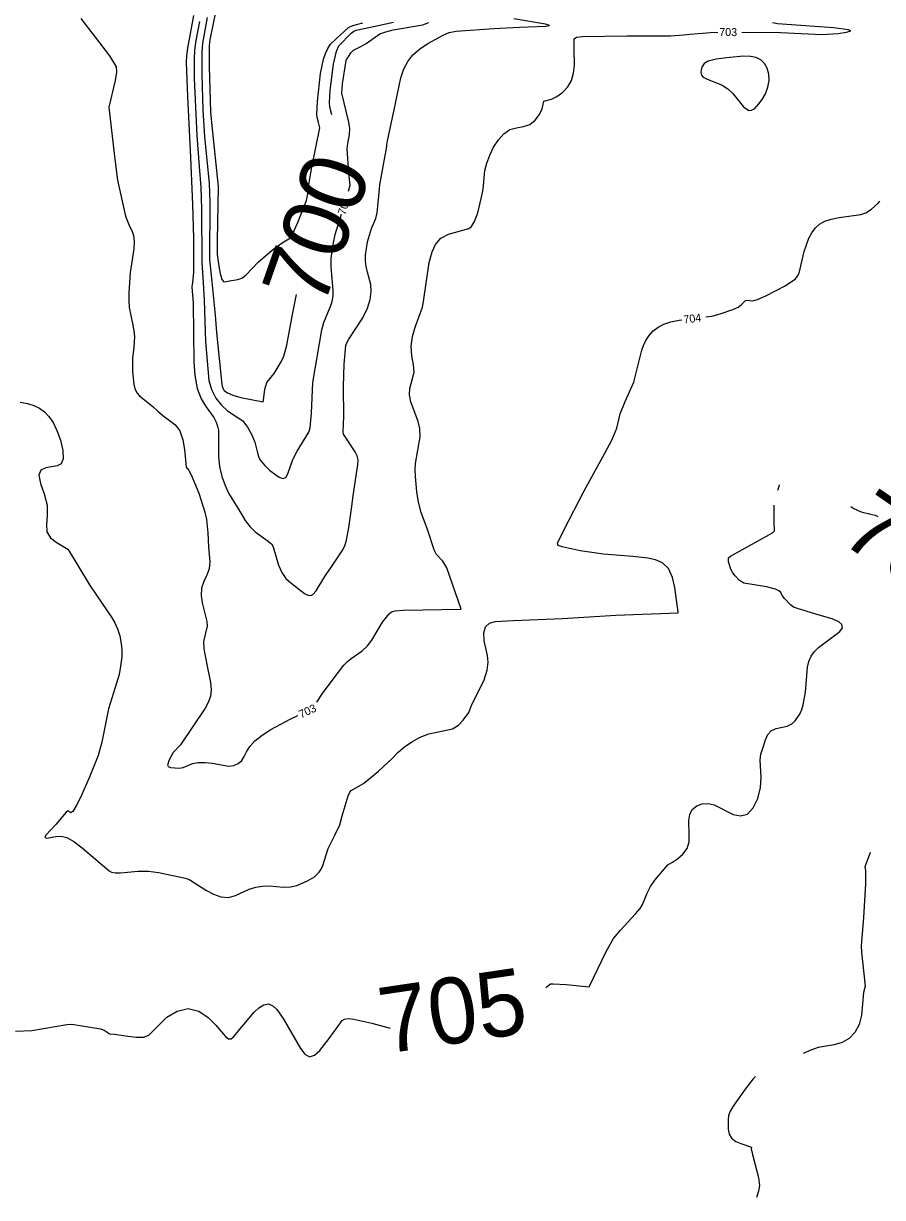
# Model space of a CAD drawing. Extents: x -291892836 to 2945206, y -477993085 to 1832792.
# Drawn here: x 1853557 to 1853987, y 544335 to 544921 of the extents above; entities that cross this region are included whole.
import ezdxf

# ---------------------------------------------------------------- set-up
doc = ezdxf.new("R2010")
doc.units = 0
for name, color, linetype in [('DT_X_Contour_Minor', 7, 'Continuous'), ('DT_X_Terrain_Ground_Line', 7, 'Continuous'), ('Level 19', 7, 'Continuous')]:
    doc.layers.add(name, color=color, linetype=linetype)

msp = doc.modelspace()

# ---------------------------------------------------------------- linework, layer by layer
at = {"layer": 'DT_X_Contour_Minor'}
for points in [[(1853585.96, 544923.91), (1853600.19, 544905.28), (1853603.63, 544899.82), (1853603.71, 544897.14), (1853603.01, 544892.88), (1853599.97, 544879.67), (1853602.72, 544854.89), (1853604.29, 544843.16), (1853608.28, 544825.1), (1853610.33, 544820.16), (1853611.4, 544817.92), (1853612.25, 544815.46), (1853612.64, 544812.49), (1853612.39, 544808.81), (1853610.66, 544796.97), (1853610, 544786.83), (1853609.92, 544783.29), (1853610.17, 544779.51), (1853611.75, 544771.47), (1853612.45, 544767.83), (1853612.71, 544764.81), (1853612.34, 544759.71), (1853611.83, 544754.16), (1853611.73, 544747.54), (1853612.39, 544741.05), (1853613.07, 544738.6), (1853614.01, 544736.74), (1853615.21, 544735.35), (1853622.15, 544729.95), (1853624.37, 544727.73), (1853626.98, 544725.5), (1853632.99, 544721.05), (1853633.91, 544719.84)], [(1853642.34, 544925.33), (1853639.2, 544909.11), (1853638.71, 544905.29), (1853638.6, 544901.98), (1853639.34, 544884.86), (1853640.71, 544854.54), (1853641.8, 544831.05), (1853642.2, 544814.23), (1853642.31, 544797.24), (1853641.82, 544792.08), (1853641.36, 544789.86), (1853642.15, 544781.74), (1853642.44, 544752.42), (1853642.98, 544745.62), (1853644.15, 544739.08), (1853646.11, 544733.94), (1853648.46, 544730.07), (1853652.4, 544724.48), (1853653.57, 544722.24), (1853654.3, 544720.22), (1853654.68, 544718.3), (1853654.77, 544713.26), (1853654.8, 544704.9), (1853655.34, 544700), (1853656.5, 544695.1), (1853658.08, 544690.56), (1853659.8, 544686.75), (1853663.03, 544681.5), (1853666.22, 544676.23), (1853668.08, 544673.1), (1853670.37, 544670.06), (1853673.17, 544667.38), (1853678.45, 544663.59), (1853681.24, 544661.52), (1853682.02, 544659.9), (1853684.7, 544650.75), (1853686.36, 544647.06), (1853687.06, 544646.11)], [(1853649.17, 544924.37), (1853646.8, 544911.58), (1853646.44, 544907.11), (1853646.36, 544895.69), (1853646.98, 544878.04), (1853647.82, 544865.03), (1853650.15, 544841.42), (1853650.38, 544832.08), (1853650.34, 544803.47), (1853651.42, 544792.36), (1853653.16, 544775.72), (1853653.71, 544767.02), (1853656.39, 544741.1), (1853656.82, 544739.49), (1853657.63, 544738.12), (1853659.19, 544736.86), (1853661.91, 544735.68), (1853665.94, 544734.59), (1853677.1, 544732.4), (1853677.24, 544733.27), (1853678, 544738.78), (1853678.95, 544742.01), (1853682.56, 544746.61), (1853686.15, 544752.45), (1853687.37, 544755.19), (1853688.9, 544760.64), (1853691.63, 544775.14), (1853693.7, 544786.01)], [(1853653.38, 544927.84), (1853650.47, 544913.18), (1853650.14, 544910.21), (1853650.11, 544899.8), (1853650.68, 544877.35), (1853651.38, 544870.27), (1853654.61, 544839.99), (1853654.13, 544812.84), (1853654.14, 544805.94), (1853654.85, 544800.17), (1853655.51, 544796.44), (1853656.36, 544793.56), (1853657.39, 544792.38), (1853658.66, 544792.43), (1853660.27, 544792.88), (1853664.37, 544793.44), (1853666.47, 544794.17), (1853668.37, 544795.64), (1853674.77, 544802.39), (1853682.58, 544808.93), (1853686.54, 544811.87), (1853690.72, 544814.35), (1853691.62, 544815.77), (1853694.44, 544822.07), (1853698.7, 544833.04), (1853699.46, 544836.24), (1853699.75, 544839.97), (1853701.47, 544849.64), (1853705.39, 544869.24), (1853704.84, 544871.98), (1853704.15, 544874.47), (1853703.98, 544876.07), (1853704.28, 544882.49), (1853705.78, 544896.38), (1853707.19, 544903.57), (1853708.21, 544906.48), (1853709.44, 544908.96), (1853710.84, 544911.01), (1853713.92, 544914.01), (1853717.83, 544917.62), (1853719.76, 544919.37), (1853721.97, 544920.46), (1853726.92, 544921.78)], [(1853735.2, 544838.78), (1853735.39, 544840.73), (1853737.42, 544851.86), (1853738.94, 544859.98), (1853738.85, 544860.72), (1853739.21, 544862.74), (1853742.62, 544878.24), (1853745.92, 544894.2), (1853747.44, 544898.69), (1853749.41, 544902.49), (1853751.99, 544905.7), (1853755.33, 544908.61), (1853759.47, 544911.42), (1853767.51, 544915.82), (1853770.11, 544916.9), (1853773.58, 544917.58), (1853792.47, 544918.97), (1853805.19, 544919.58), (1853818.36, 544920.04), (1853820.21, 544920.43), (1853818.33, 544921.03), (1853802.45, 544923.79)], [(1853645.28, 544922.46), (1853643.47, 544912.94), (1853642.82, 544908.11), (1853642.51, 544903.46), (1853642.61, 544894.01), (1853643.92, 544865.38), (1853645.12, 544849.95), (1853645.85, 544839.63), (1853646.19, 544828.58), (1853646.4, 544801.97), (1853647.02, 544791.92), (1853647.66, 544783.13), (1853648.18, 544762.54), (1853649.89, 544743.12), (1853651.19, 544738.49), (1853653.43, 544734.25), (1853656.29, 544730.66), (1853659.26, 544727.97), (1853666.85, 544722.85), (1853669.25, 544719.73), (1853671.39, 544715.96), (1853672.98, 544712.28)], [(1853711.42, 544875.75), (1853710.41, 544879.69), (1853710.25, 544881.87), (1853710.61, 544887.94), (1853712.33, 544901.05), (1853713.68, 544907.55), (1853715, 544910.23), (1853721.17, 544916.54), (1853722.41, 544917.65), (1853723.56, 544918.06), (1853730.77, 544919.63), (1853742.29, 544922.12)], [(1853719.72, 544837.68), (1853720.62, 544840.67), (1853719.94, 544846.78), (1853719.1, 544858.84), (1853719.51, 544861.44), (1853720.33, 544865.91), (1853720.36, 544868.89), (1853719.88, 544872.12), (1853716.37, 544886.68), (1853716.81, 544891.26), (1853718.58, 544902.87), (1853719.36, 544904.68), (1853719.7, 544904.81), (1853720.93, 544906.75), (1853722.19, 544908.03), (1853726.34, 544910.17), (1853728.66, 544911.39), (1853735.41, 544916.19), (1853738.37, 544917.32), (1853742.07, 544918.17), (1853756.98, 544920.76), (1853759.99, 544921.85)], [(1853916.39, 544917.08), (1853935.73, 544916.91), (1853956.45, 544915.92), (1853964.64, 544916.5), (1853968.83, 544917.05), (1853970.92, 544917.67), (1853969.73, 544918.26), (1853962.31, 544919.19), (1853934.33, 544921.21), (1853931.78, 544921.73)], [(1853832.66, 544908.76), (1853832.66, 544908.78), (1853832.63, 544913.79), (1853833.75, 544914.64), (1853836.73, 544914.94), (1853858.95, 544915.22), (1853870.34, 544915.22), (1853880.74, 544915.28), (1853887.25, 544915.76)], [(1853887.25, 544915.76), (1853890.61, 544916.01), (1853900.78, 544917), (1853904.39, 544917.06)], [(1853703.92, 544582.31), (1853706.69, 544586.74), (1853712.55, 544594.55), (1853717.49, 544600.76), (1853719.23, 544602.62), (1853721.17, 544604.21), (1853726.56, 544608.04), (1853729.23, 544610.5), (1853731.36, 544613.38), (1853736.78, 544622.35), (1853740.11, 544626.44), (1853741.22, 544627.5), (1853743.1, 544628.02), (1853747.2, 544628.24), (1853776.16, 544628.74), (1853768.87, 544649.51), (1853766.86, 544652.7), (1853763.71, 544656.1), (1853762.63, 544658.46), (1853759.33, 544668.61), (1853756.06, 544677.05), (1853754.83, 544682.2), (1853753.92, 544687.41), (1853753.19, 544695.01), (1853753.12, 544698.63), (1853753.34, 544701.54), (1853755.52, 544714.98), (1853755.43, 544719.01), (1853754.63, 544722.52), (1853750.96, 544732.38), (1853750.34, 544735.85), (1853750.39, 544739.02), (1853752.6, 544747.15), (1853752.21, 544750.91), (1853751.47, 544755.34), (1853751.16, 544760.16), (1853751.83, 544765.06), (1853753.14, 544769.64), (1853756.74, 544779.67), (1853757.24, 544782.56), (1853760.1, 544801.97), (1853761.55, 544807.36), (1853763.21, 544810.96), (1853765.92, 544814.1), (1853769.77, 544816.11), (1853780, 544819), (1853781.29, 544820.04), (1853782.75, 544822.49), (1853784.37, 544826.87), (1853786.35, 544834.68), (1853787.05, 544838.67), (1853787.94, 544848.01), (1853788.89, 544851.62), (1853790.38, 544855.58), (1853792.33, 544859.56), (1853794.69, 544863.24), (1853797.42, 544866.3), (1853800.48, 544868.38), (1853803.82, 544869.36), (1853807.21, 544869.93), (1853810.4, 544870.99), (1853813.13, 544873.17), (1853815.25, 544875.99), (1853816.61, 544878.7), (1853817.46, 544882.57), (1853821.26, 544883.54), (1853823.94, 544884.94), (1853826.87, 544887.08), (1853829.45, 544889.8), (1853831.22, 544892.98), (1853832.24, 544896.57), (1853832.7, 544900.55), (1853832.66, 544908.76)], [(1853920, 544877.91), (1853921.31, 544878.1), (1853922.75, 544878.85), (1853924.94, 544881.23), (1853926.56, 544883.47), (1853928.22, 544886.31), (1853929.51, 544889.53), (1853930.08, 544892.9), (1853929.94, 544896.18), (1853929.17, 544899.11), (1853927.83, 544901.5), (1853925.96, 544903.28), (1853923.58, 544904.43), (1853920.71, 544904.98), (1853917.45, 544905.05), (1853910.21, 544904.45), (1853903.61, 544903.52), (1853899.64, 544902.57), (1853897.62, 544901.39), (1853896.51, 544899.56), (1853896.1, 544898.3), (1853895.94, 544896.93), (1853896.24, 544895.65), (1853897.15, 544894.59), (1853898.71, 544893.7), (1853906.53, 544890.65), (1853909.39, 544888.85), (1853911.89, 544886.39), (1853917.33, 544879.7), (1853920, 544877.91)], [(1853710.88, 544649.44), (1853716.68, 544658.01), (1853717.92, 544660.52), (1853718.81, 544663.32), (1853719.99, 544669.65), (1853721.39, 544680.09), (1853721.87, 544684.21), (1853724.51, 544701.04), (1853724.59, 544703.39), (1853724.14, 544705.34), (1853723.13, 544707.33), (1853717.24, 544716.27), (1853717.04, 544717.6), (1853717.44, 544724.96), (1853717.21, 544740.07), (1853717.61, 544751.21), (1853718.43, 544760.46), (1853718.77, 544761.58), (1853720, 544763.66), (1853726.86, 544774.42), (1853729.25, 544779.21), (1853730.63, 544783.6), (1853731.09, 544787.52), (1853730.86, 544791.03), (1853729.31, 544797.15), (1853728.59, 544799.96), (1853728.24, 544802.75), (1853728.28, 544805.65), (1853729.33, 544812.28), (1853731.26, 544818.91), (1853733.35, 544823.95), (1853734.1, 544826.86), (1853734.86, 544835.37), (1853735.2, 544838.78)], [(1853898.39, 544774.81), (1853901.4, 544775.15), (1853905.6, 544776.28), (1853911.91, 544778.52), (1853914.58, 544779.76), (1853916.17, 544780.86), (1853918.21, 544782.95), (1853919, 544783.16), (1853921.84, 544782.77), (1853924.35, 544783.49), (1853928.44, 544785.31), (1853937.78, 544790.24), (1853943.12, 544793.69), (1853944.36, 544795.1), (1853945.05, 544796.67), (1853947.62, 544807.5), (1853950.02, 544814.11), (1853951.47, 544816.9), (1853953.21, 544819.27), (1853955.32, 544821.16), (1853957.93, 544822.63), (1853961.18, 544823.73), (1853965.09, 544824.53), (1853975.87, 544825.95), (1853978.44, 544826.8), (1853981.23, 544828.57), (1853984.59, 544831.57), (1853985.47, 544832.57)], [(1853672.98, 544712.28), (1853674.24, 544706.96), (1853674.74, 544705), (1853675.65, 544703.26), (1853677.94, 544700.5), (1853680.22, 544698.21), (1853683.46, 544695.88), (1853685.12, 544694.79), (1853686.85, 544694.1), (1853688.35, 544694.51), (1853689.45, 544696.49), (1853691.94, 544703.62), (1853694.08, 544707.7), (1853699.92, 544717.16), (1853700.61, 544719.42), (1853701.23, 544726.7), (1853701.9, 544741.99), (1853706.49, 544768.37), (1853707.38, 544772.04), (1853709.73, 544777.66), (1853710.83, 544780.05), (1853711.63, 544782.47), (1853712.07, 544785.11), (1853712.12, 544788.17), (1853711.08, 544799.88), (1853711.16, 544803.94), (1853712.06, 544811.04), (1853713.16, 544815.94), (1853716.25, 544826.19)], [(1853676.74, 544490.48), (1853680.18, 544490.52), (1853687.27, 544489.95), (1853690.7, 544490.03), (1853693.9, 544490.71), (1853699.2, 544493.01), (1853702.69, 544495.07), (1853705.12, 544497.33), (1853706.12, 544498.85), (1853706.98, 544500.78), (1853709.64, 544509.21), (1853712.93, 544515.92), (1853715.37, 544520.98), (1853716.66, 544525.51), (1853719.59, 544535.52), (1853720.35, 544537.35), (1853721.03, 544538.24), (1853727.2, 544541.75), (1853734.83, 544547.82), (1853741.83, 544554.42), (1853744.66, 544557.27), (1853747.7, 544559.95), (1853751.37, 544562.54), (1853755.52, 544564.81), (1853759.86, 544566.45), (1853771.73, 544569.02), (1853774.77, 544570.92), (1853777.18, 544573.29), (1853779.93, 544577.16), (1853780.78, 544579.4), (1853781.25, 544580.73), (1853787.54, 544593.52), (1853789.18, 544598.32), (1853789.64, 544602.26), (1853789.21, 544605.67), (1853787.67, 544613.06), (1853787.49, 544616.92), (1853788.28, 544620.01), (1853790.28, 544621.81), (1853793.09, 544622.6), (1853802.08, 544623.12), (1853826.73, 544624.12), (1853853.37, 544625.76), (1853884.53, 544627.04), (1853884.65, 544627.35), (1853882.94, 544639.65), (1853881.73, 544644.67), (1853879.74, 544649.04), (1853876.82, 544651.91), (1853873.26, 544653.51), (1853869.5, 544654.35), (1853861.99, 544655.17), (1853847.28, 544656.3), (1853835.64, 544657.96), (1853826.59, 544659.88), (1853824.61, 544660.61), (1853824.33, 544661.78), (1853827.45, 544668.3), (1853837.54, 544687.9), (1853847.96, 544706.73), (1853851.47, 544713.32), (1853853.92, 544719.23), (1853855.54, 544726.38), (1853858.04, 544732.53), (1853862.51, 544742.2), (1853865.18, 544752.95), (1853866.48, 544758.23), (1853867.3, 544760.49), (1853868.49, 544762.96), (1853870.09, 544765.49), (1853872.1, 544767.81), (1853874.54, 544769.71), (1853877.48, 544771.2), (1853880.98, 544772.33), (1853885.04, 544773.17), (1853886.47, 544773.36)], [(1853555.57, 544732.16), (1853559.22, 544731.56), (1853562.44, 544730.58), (1853565.24, 544729.2), (1853567.72, 544727.39), (1853569.99, 544725.1), (1853572.06, 544722.11), (1853573.98, 544718.15), (1853575.69, 544713.19), (1853576.88, 544708.08), (1853577.13, 544703.91), (1853576.16, 544701.48), (1853574.17, 544700.38), (1853568.44, 544699.43), (1853565.93, 544698.25), (1853564.85, 544695.78), (1853565.74, 544691.62), (1853567.6, 544686.35), (1853569.06, 544680.8), (1853569.17, 544675.65), (1853568.73, 544671.15), (1853568.99, 544667.4), (1853570.82, 544664.48), (1853573.53, 544662.33), (1853579.39, 544658.78), (1853580.14, 544657.83), (1853583.96, 544651.52), (1853590.33, 544640.91), (1853596.59, 544631.58), (1853601.31, 544624.84), (1853602.99, 544622.02), (1853604.32, 544618.99), (1853605.36, 544615.44), (1853606.1, 544611.65), (1853606.47, 544608.07), (1853606.46, 544605.04), (1853605.83, 544600.35), (1853605.03, 544596.19), (1853603.15, 544589.67), (1853599.75, 544578.97), (1853596.45, 544562.31), (1853594.52, 544555.65), (1853590.01, 544544.5), (1853585.71, 544534.76), (1853583.6, 544530.51), (1853581.91, 544527.78), (1853580.85, 544527.1), (1853579.49, 544527.99), (1853578.55, 544527.37), (1853573.45, 544521.15), (1853568.38, 544515.81), (1853567.84, 544514.64), (1853568.8, 544514.39), (1853573.42, 544515.21), (1853576.02, 544515.33), (1853578.88, 544514.66), (1853582.34, 544512.77), (1853586.59, 544509.5), (1853600.09, 544498), (1853601.29, 544497.46), (1853603.02, 544497.12), (1853605.72, 544497.11), (1853614.52, 544497.87), (1853619.71, 544497.9), (1853624.74, 544497.29), (1853638.3, 544494.36), (1853640.46, 544493.56), (1853645.62, 544490.31), (1853648.75, 544488.3), (1853652.26, 544486.44), (1853655.97, 544485.12), (1853659.69, 544484.78), (1853663.26, 544485.67), (1853670.05, 544488.9), (1853673.38, 544489.98), (1853676.74, 544490.48)], [(1853633.91, 544719.84), (1853635.44, 544717.82), (1853636.94, 544713.4), (1853637.69, 544708.62), (1853638.56, 544699.69), (1853639.01, 544699.15), (1853639.35, 544698.95), (1853639.97, 544698.13), (1853641.09, 544695.92), (1853644.86, 544686.74), (1853647.98, 544677.3), (1853648.76, 544673.67), (1853649.39, 544666.94), (1853649.77, 544659.83), (1853650.4, 544652.45), (1853650.04, 544648.97), (1853648.86, 544645.76), (1853648.58, 544645.17)], [(1853934.49, 544688.29), (1853935.28, 544690.75), (1853935.34, 544690.9)], [(1853818.41, 544439.77), (1853820.84, 544441.54), (1853822.15, 544441.66), (1853828.62, 544441.24), (1853840.08, 544440.13), (1853848.66, 544457.75), (1853852.3, 544464.22), (1853855.79, 544468.48), (1853863.33, 544476.58), (1853865.62, 544479.25), (1853866.72, 544481.17), (1853869.03, 544486.9), (1853870.72, 544490.23), (1853872.97, 544493.48), (1853879.39, 544501.11), (1853881.72, 544502.39), (1853884.22, 544504.04), (1853887, 544506.37), (1853889.18, 544509.27), (1853890.13, 544512.59), (1853890.19, 544516.15), (1853889.91, 544523.17), (1853890.4, 544526.25), (1853891.67, 544528.78), (1853893.86, 544530.59), (1853896.66, 544531.6), (1853899.66, 544531.73), (1853902.54, 544530.97), (1853912.09, 544526.28), (1853915.74, 544525.52), (1853919.2, 544526.44), (1853922.15, 544529.55), (1853924.38, 544534.26), (1853925.7, 544539.63), (1853926.06, 544544.87), (1853925.69, 544553.42), (1853925.94, 544556.28), (1853927.38, 544560.86), (1853928.29, 544563.53), (1853929.47, 544566.17), (1853931.21, 544568.2), (1853933.65, 544569.23), (1853939.16, 544570.27), (1853941.38, 544571.44), (1853943.13, 544573.09), (1853945.59, 544576.71), (1853946.45, 544578.66), (1853947.16, 544581.04), (1853948.25, 544587.36), (1853949.3, 544599.88), (1853949.99, 544602.66), (1853951.1, 544605.27), (1853952.7, 544607.62), (1853954.83, 544609.66), (1853965.51, 544617.57), (1853966.75, 544619.5), (1853966.44, 544621.13), (1853965.03, 544622.41), (1853961.57, 544623.92), (1853955.06, 544625.82), (1853944.71, 544629.02), (1853942.34, 544629.81), (1853940.73, 544630.9), (1853937.71, 544634.15), (1853936.65, 544635.7), (1853935.98, 544637.2), (1853935.01, 544638.03), (1853933.35, 544638.77), (1853928.74, 544639.92), (1853917.37, 544641.87), (1853915.34, 544643.08), (1853913.13, 544645.38), (1853911.96, 544646.98), (1853910.96, 544648.77), (1853909.85, 544652.37), (1853909.73, 544654.5), (1853910.75, 544655.34), (1853931.76, 544666.93), (1853932.74, 544668.02), (1853932.69, 544672.23), (1853932.57, 544678.85), (1853932.68, 544680.82)], [(1853970.93, 544680.04), (1853972.46, 544679.03), (1853976.06, 544677.5), (1853981.54, 544676.18), (1853983.16, 544675.83), (1853984.19, 544675.3), (1853984.38, 544674.99)], [(1853708.98, 544646.64), (1853710.88, 544649.44)], [(1853648.58, 544645.17), (1853647.37, 544642.64), (1853646.28, 544639.35), (1853646.11, 544635.71), (1853646.66, 544631.96), (1853648.95, 544622.65), (1853649.01, 544620.26), (1853647.22, 544612.64), (1853647.39, 544608.93), (1853649.06, 544600.29), (1853650.84, 544592.09), (1853651.16, 544588.53), (1853650.83, 544585.39), (1853649.81, 544582.42), (1853648.12, 544579.3), (1853635.76, 544561), (1853632.07, 544557.19), (1853630.04, 544553.59), (1853629.2, 544550.82), (1853629.6, 544550.15), (1853630.75, 544549.75), (1853635.02, 544549.42), (1853637.1, 544549.66), (1853641.78, 544551.71), (1853644.64, 544552.11), (1853648.1, 544552.16), (1853651.61, 544551.86), (1853659.98, 544550.33), (1853662.44, 544550.69), (1853664.67, 544551.68), (1853666.43, 544553.23), (1853667.64, 544555.24), (1853668.76, 544557.6), (1853670.39, 544560.23), (1853673.01, 544563.01), (1853676.57, 544565.86), (1853680.91, 544568.7), (1853690.54, 544573.79), (1853694.5, 544575.66)], [(1853687.06, 544646.11), (1853688.49, 544644.16), (1853690.89, 544641.92), (1853697.71, 544636.68), (1853699.47, 544635.76), (1853700.89, 544635.63), (1853702.01, 544636.11), (1853703.56, 544637.98), (1853707.9, 544645.04), (1853708.98, 544646.64)], [(1853980.65, 544507.36), (1853980.37, 544506.7), (1853977.97, 544500.02), (1853978.22, 544498.21), (1853978.24, 544491.55), (1853977.33, 544474.7), (1853976.17, 544460.51), (1853976.35, 544457.49), (1853978.14, 544440.48), (1853977.28, 544437.23), (1853976.22, 544425.91), (1853975.06, 544421.25), (1853972.98, 544417.3), (1853970.1, 544414.27), (1853966.58, 544412.23), (1853962.63, 544411.15), (1853954.57, 544409.82), (1853950.95, 544408.54), (1853947.14, 544406.73)], [(1853553.3, 544417.98), (1853561.35, 544418.29), (1853578.86, 544421.21), (1853581.38, 544421.39), (1853587.62, 544420.51), (1853595.71, 544419.09), (1853597.61, 544418.5), (1853599.63, 544417.1), (1853600.31, 544416.62), (1853602.78, 544416.39), (1853609.35, 544415.5), (1853613.75, 544414.94), (1853617.58, 544414.98), (1853620.17, 544416.06), (1853629, 544424.87), (1853634.1, 544428.02), (1853639.59, 544429.36), (1853644.87, 544428.01), (1853649.59, 544424.8), (1853653.45, 544420.99), (1853658.26, 544415.28), (1853659.76, 544414.05), (1853661.06, 544414.1), (1853662.24, 544415.05), (1853672.6, 544427.45), (1853674.95, 544429.61), (1853677.37, 544431.16), (1853679.75, 544431.61), (1853681.97, 544430.68), (1853683.97, 544428.77), (1853687.11, 544424.21), (1853695.69, 544409.28), (1853697.87, 544406.52), (1853700.27, 544405.2), (1853702.84, 544405.99), (1853705.44, 544408.33), (1853710.08, 544414.32), (1853716.63, 544423.22), (1853717.77, 544423.93), (1853719.55, 544424.25), (1853722.46, 544423.99), (1853731.48, 544421.89), (1853740.68, 544419.52)], [(1853923.24, 544395.28), (1853922.14, 544394.18), (1853918.13, 544388.99), (1853912.08, 544380.53), (1853910.64, 544378.02), (1853909.85, 544375.79), (1853909.56, 544373.68), (1853909.64, 544369.02), (1853910.12, 544366.56), (1853911.34, 544364.42), (1853913.46, 544362.83), (1853915.99, 544361.75), (1853921.21, 544360.02), (1853921.03, 544359.11), (1853921.72, 544356.27), (1853924.8, 544344.84), (1853925.3, 544340.93), (1853924.73, 544337.95), (1853923.74, 544334.84)]]:
    msp.add_lwpolyline(points, dxfattribs=at)

# ---------------------------------------------------------------- texts
at = {"layer": 'DT_X_Terrain_Ground_Line'}
for s, rotation, p in [('700', 70.57121, (1853706.97, 544778.6)), ('705', 325.33689, (1853964.61, 544663.22)), ('705', 8.40848, (1853737.69, 544406.58))]:
    msp.add_text(s, height=33, rotation=rotation, dxfattribs=at).set_placement(p)
at = {"layer": 'Level 19'}
for s, rotation, p in [('703', 359.49091, (1853905.14, 544915.18)), ('701', 73.21255, (1853718.13, 544825.48)), ('704', 7.31667, (1853887.51, 544771.47)), ('703', 25.2216, (1853696.05, 544574.18))]:
    msp.add_text(s, height=4, rotation=rotation, dxfattribs=at).set_placement(p)

doc.saveas('drawing.dxf')
